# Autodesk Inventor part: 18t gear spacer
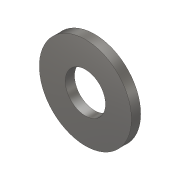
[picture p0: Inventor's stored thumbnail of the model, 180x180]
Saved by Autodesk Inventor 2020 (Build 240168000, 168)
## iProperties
Created: 2018-01
Part Number: 18t gear spacer
Material: Steel, Alloy
Document SubType Name: Modeling
Designer: Kevin
Density: 7.73 g/cm^3
Appearance: Semi-Polished
Vendor: KoP
Mass: 8.04453 g
Surface Area: 11.108 cm^2
Volume: 1.04069 cm^3
Author: Kevin
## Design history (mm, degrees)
sketch "Sketch1"
  geometry: C1 r 12.7 at (0, 0); C2 r 5.556 at (0, 0); 1 further point
  constraints: 2 centre point, 2 coincident
  dimensions: "d0" = 11.1125 diameter of C2; "d1" = 25.4 diameter of C1
extrude "Extrusion1" new body sketch "Sketch1" distance "d2" = 2.54; taper "d3" = 0 deg
body "Solid1"
